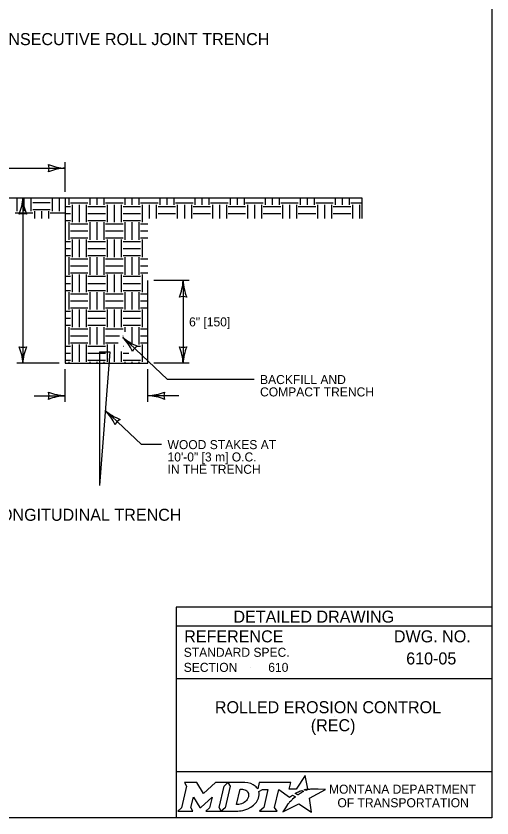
# Model space of a CAD drawing. Extents: x 49977.1 to 50021, y 49987.6 to 50011.4.
# Drawn here: x 50013.59 to 50016.75, y 49987.8 to 49993.13 of the extents above; entities that cross this region are included whole.
import ezdxf

# ---------------------------------------------------------------- set-up
doc = ezdxf.new("R2010")
doc.units = 0
for name, color, linetype in [('Default', 7, 'Continuous'), ('Level 1', 7, 'Continuous'), ('Level 2', 7, 'Continuous'), ('Level 3', 7, 'Continuous'), ('Level 5', 7, 'Continuous')]:
    doc.layers.add(name, color=color, linetype=linetype)

msp = doc.modelspace()

# ---------------------------------------------------------------- linework, layer by layer
at = {"layer": 'Default'}
for points in [[(50015.5126, 49987.9811), (50015.5023, 49987.9867), (50015.5139, 49987.9895), (50015.5255, 49987.9915), (50015.5081, 49988.0816), (50015.4486, 49987.9903), (50015.4013, 49987.9896), (50015.4116, 49988.0337), (50015.2024, 49988.0338), (50015.1923, 49987.9913), (50015.1865, 49987.9996)], [(50014.7056, 49988.0338), (50014.7197, 49988.0104), (50014.6862, 49987.8671), (50014.6605, 49987.8446), (50014.7621, 49987.8446), (50014.7486, 49987.8674), (50014.7648, 49987.9375), (50014.8085, 49987.8685), (50014.8138, 49987.8685), (50014.8889, 49987.938), (50014.8725, 49987.8669), (50014.8478, 49987.8449), (50014.9494, 49987.8449), (50014.9356, 49987.8682), (50014.9688, 49988.0106)], [(50014.9688, 49988.0106), (50014.9941, 49988.0338), (50014.9117, 49988.0338), (50014.8321, 49987.9608), (50014.7876, 49988.0335), (50014.7056, 49988.0338)], [(50015.1077, 49988.0338), (50014.9941, 49988.0338), (50015.0088, 49988.0109), (50014.9749, 49987.8671), (50014.9494, 49987.8449), (50015.06, 49987.8449)], [(50015.1317, 49987.9471), (50015.1305, 49987.939), (50015.1273, 49987.9297), (50015.1231, 49987.9215), (50015.1175, 49987.914), (50015.111, 49987.9071), (50015.1031, 49987.9008), (50015.0948, 49987.8961), (50015.0857, 49987.8922), (50015.0766, 49987.8899), (50015.0674, 49987.889), (50015.0515, 49987.889), (50015.0751, 49987.989), (50015.0911, 49987.989), (50015.0987, 49987.9884), (50015.1063, 49987.9865), (50015.1129, 49987.9835), (50015.119, 49987.9793), (50015.1238, 49987.9743), (50015.1275, 49987.9683), (50015.1302, 49987.9621), (50015.1318, 49987.9547), (50015.1318, 49987.9517), (50015.1317, 49987.9471)], [(50015.1991, 49987.9747), (50015.2237, 49987.9878), (50015.2606, 49987.9878), (50015.232, 49987.8673), (50015.2045, 49987.8446), (50015.3207, 49987.8446), (50015.3037, 49987.8675), (50015.3319, 49987.9877), (50015.4032, 49987.936), (50015.4243, 49987.9511), (50015.444, 49987.9402)], [(50015.3882, 49987.8843), (50015.3729, 49987.8599), (50015.3682, 49987.8524), (50015.3624, 49987.8438), (50015.3601, 49987.8395), (50015.4654, 49987.8926), (50015.5493, 49987.8375), (50015.5362, 49987.9302), (50015.6431, 49987.9886), (50015.5938, 49987.9894), (50015.5637, 49987.9898), (50015.5429, 49987.9901), (50015.5361, 49987.9886), (50015.5312, 49987.9874), (50015.5228, 49987.9851), (50015.5126, 49987.9811)], [(50015.4622, 49987.9535), (50015.4598, 49987.9518), (50015.4415, 49987.9614), (50015.4518, 49987.9671), (50015.4559, 49987.9693), (50015.4645, 49987.9733), (50015.4702, 49987.9759), (50015.4781, 49987.9789), (50015.4854, 49987.9816), (50015.4972, 49987.9742), (50015.4932, 49987.9721), (50015.4886, 49987.9696), (50015.4844, 49987.9674), (50015.4794, 49987.9645), (50015.4775, 49987.9634), (50015.4748, 49987.9618), (50015.4723, 49987.9604), (50015.47, 49987.9588), (50015.4674, 49987.957), (50015.4647, 49987.9552), (50015.4622, 49987.9535)], [(50015.4021, 49987.9004), (50015.4021, 49987.9004)], [(50015.1057, 49987.8522), (50015.1141, 49987.8548), (50015.1271, 49987.8602), (50015.1475, 49987.8712)]]:
    msp.add_lwpolyline(points, dxfattribs=at)
for centre, radius, start, end in [((50015.1308, 49987.9554), 0.0709, 339.5329, 15.8582), ((50015.0868, 49987.9727), 0.1183, 300.9103, 339.1383)]:
    msp.add_arc(centre, radius, start, end, dxfattribs=at)
for centre, major_axis, ratio, start_param, end_param in [((50015.1056, 49987.9864), (0.0834, -0.0037), 0.568097, 0.61298, 1.570796), ((50015.1612, 49987.9937), (0.0361, -0.0295), 0.469099, 1.225588, 1.570796), ((50015.3952, 49987.8923), (-0.00694, -0.00806), 0.008222, 0, 3.137361), ((50015.4119, 49987.9106), (-0.0098, -0.0102), 0.016458, 3.141593, 6.279097), ((50015.4329, 49987.9305), (-0.0112, -0.0097), 0.021651, 3.157348, 6.283185), ((50015.0603, 49987.9932), (0, 0.1484), 0.987302, 3.139398, 3.456847)]:
    msp.add_ellipse(centre, major_axis=major_axis, ratio=ratio, start_param=start_param, end_param=end_param, dxfattribs=at)
at = {"layer": 'Level 1'}
for p, q in [((50013.5917, 49991.9196), (50013.5917, 49991.8293)), ((50013.6383, 49991.9196), (50013.6383, 49991.8293)), ((50013.6849, 49991.9196), (50013.6849, 49991.8293)), ((50013.8247, 49991.9196), (50013.8247, 49991.8293)), ((50013.8713, 49991.9196), (50013.8713, 49991.8293)), ((50013.912, 49991.9196), (50015.8855, 49991.9196)), ((50013.9365, 49991.9196), (50013.9365, 49991.8725)), ((50014.0762, 49991.9196), (50014.0762, 49991.8725)), ((50014.1228, 49991.9196), (50014.1228, 49991.8725)), ((50014.1694, 49991.9196), (50014.1694, 49991.8725)), ((50014.3092, 49991.9196), (50014.3092, 49991.8725)), ((50014.3558, 49991.9196), (50014.3558, 49991.8725)), ((50014.4024, 49991.9196), (50014.4024, 49991.8725)), ((50014.5422, 49991.9196), (50014.5422, 49991.8725)), ((50014.5888, 49991.9196), (50014.5888, 49991.8725)), ((50014.6354, 49991.9196), (50014.6354, 49991.8725)), ((50014.7752, 49991.9196), (50014.7752, 49991.8725)), ((50014.8218, 49991.9196), (50014.8218, 49991.8725)), ((50014.8684, 49991.9196), (50014.8684, 49991.8725)), ((50015.0082, 49991.9196), (50015.0082, 49991.8725)), ((50015.0548, 49991.9196), (50015.0548, 49991.8725)), ((50015.1014, 49991.9196), (50015.1014, 49991.8725)), ((50015.2412, 49991.9196), (50015.2412, 49991.8725)), ((50015.2878, 49991.9196), (50015.2878, 49991.8725)), ((50015.3344, 49991.9196), (50015.3344, 49991.8725)), ((50015.4742, 49991.9196), (50015.4742, 49991.8725)), ((50015.5208, 49991.9196), (50015.5208, 49991.8725)), ((50015.5674, 49991.9196), (50015.5674, 49991.8725)), ((50015.7072, 49991.9196), (50015.7072, 49991.8725)), ((50015.7538, 49991.9196), (50015.7538, 49991.8725)), ((50015.8004, 49991.9196), (50015.8004, 49991.8725)), ((50015.8855, 49991.9196), (50015.8855, 49991.7821)), ((50013.6965, 49991.8876), (50013.813, 49991.8876)), ((50013.6965, 49991.841), (50013.813, 49991.841)), ((50013.912, 49991.8617), (50013.9472, 49991.8617)), ((50013.9472, 49991.885), (50014.0637, 49991.885)), ((50013.9589, 49991.8733), (50013.9589, 49991.7568)), ((50014.0055, 49991.8733), (50014.0055, 49991.7568)), ((50014.0521, 49991.8733), (50014.0521, 49991.7568)), ((50014.0637, 49991.8617), (50014.1802, 49991.8617)), ((50014.1802, 49991.885), (50014.2967, 49991.885)), ((50014.1919, 49991.8733), (50014.1919, 49991.7568)), ((50014.2385, 49991.8733), (50014.2385, 49991.7568)), ((50014.2851, 49991.8733), (50014.2851, 49991.7568)), ((50014.2967, 49991.8617), (50014.4132, 49991.8617)), ((50014.4132, 49991.885), (50014.5297, 49991.885)), ((50014.4249, 49991.8733), (50014.4249, 49991.7568)), ((50014.4715, 49991.8733), (50014.4715, 49991.7821)), ((50014.5181, 49991.8733), (50014.5181, 49991.7821)), ((50014.5297, 49991.8617), (50014.6462, 49991.8617)), ((50014.6462, 49991.885), (50014.7627, 49991.885)), ((50014.6579, 49991.8733), (50014.6579, 49991.7821)), ((50014.7045, 49991.8733), (50014.7045, 49991.7821)), ((50014.7511, 49991.8733), (50014.7511, 49991.7821)), ((50014.7627, 49991.8617), (50014.8792, 49991.8617)), ((50014.8792, 49991.885), (50014.9957, 49991.885)), ((50014.8909, 49991.8733), (50014.8909, 49991.7821)), ((50014.9375, 49991.8733), (50014.9375, 49991.7821)), ((50014.9841, 49991.8733), (50014.9841, 49991.7821)), ((50014.9957, 49991.8617), (50015.1122, 49991.8617)), ((50015.1122, 49991.885), (50015.2287, 49991.885)), ((50015.1239, 49991.8733), (50015.1239, 49991.7821)), ((50015.1705, 49991.8733), (50015.1705, 49991.7821)), ((50015.2171, 49991.8733), (50015.2171, 49991.7821)), ((50015.2287, 49991.8617), (50015.3452, 49991.8617)), ((50015.3452, 49991.885), (50015.4617, 49991.885)), ((50015.3569, 49991.8733), (50015.3569, 49991.7821)), ((50015.4035, 49991.8733), (50015.4035, 49991.7821)), ((50015.45, 49991.8733), (50015.45, 49991.7821)), ((50015.4617, 49991.8617), (50015.5782, 49991.8617)), ((50015.5782, 49991.885), (50015.6947, 49991.885)), ((50015.5898, 49991.8733), (50015.5898, 49991.7821)), ((50015.6364, 49991.8733), (50015.6364, 49991.7821)), ((50015.683, 49991.8733), (50015.683, 49991.7821)), ((50015.6947, 49991.8617), (50015.8112, 49991.8617)), ((50015.8112, 49991.885), (50015.8855, 49991.885)), ((50015.8228, 49991.8733), (50015.8228, 49991.7821)), ((50015.8694, 49991.8733), (50015.8694, 49991.7821)), ((50013.58, 49991.8185), (50013.6965, 49991.8185)), ((50013.709, 49991.8293), (50013.709, 49991.7821)), ((50013.7556, 49991.8293), (50013.7556, 49991.7821)), ((50013.8022, 49991.8293), (50013.8022, 49991.7821)), ((50013.813, 49991.8185), (50013.912, 49991.8185)), ((50013.912, 49991.8151), (50013.9472, 49991.8151)), ((50014.0637, 49991.8151), (50014.1802, 49991.8151)), ((50014.2967, 49991.8151), (50014.4132, 49991.8151)), ((50014.5297, 49991.8151), (50014.6462, 49991.8151)), ((50014.7627, 49991.8151), (50014.8792, 49991.8151)), ((50014.9957, 49991.8151), (50015.1122, 49991.8151)), ((50015.2287, 49991.8151), (50015.3452, 49991.8151)), ((50015.4617, 49991.8151), (50015.5782, 49991.8151)), ((50015.6947, 49991.8151), (50015.8112, 49991.8151)), ((50013.912, 49991.7685), (50013.9472, 49991.7685)), ((50013.9365, 49991.7568), (50013.9365, 49991.6403)), ((50013.9472, 49991.746), (50014.0637, 49991.746)), ((50014.0637, 49991.7685), (50014.1802, 49991.7685)), ((50014.0762, 49991.7568), (50014.0762, 49991.6403)), ((50014.1228, 49991.7568), (50014.1228, 49991.6403)), ((50014.1694, 49991.7568), (50014.1694, 49991.6403)), ((50014.1802, 49991.746), (50014.2967, 49991.746)), ((50014.2967, 49991.7685), (50014.4132, 49991.7685)), ((50014.3092, 49991.7568), (50014.3092, 49991.6403)), ((50014.3558, 49991.7568), (50014.3558, 49991.6403)), ((50014.4024, 49991.7568), (50014.4024, 49991.6403)), ((50014.4132, 49991.746), (50014.462, 49991.746)), ((50013.9472, 49991.6994), (50014.0637, 49991.6994)), ((50014.1802, 49991.6994), (50014.2967, 49991.6994)), ((50014.4132, 49991.6994), (50014.462, 49991.6994)), ((50013.912, 49991.6295), (50013.9472, 49991.6295)), ((50013.9472, 49991.6528), (50014.0637, 49991.6528)), ((50013.9589, 49991.6411), (50013.9589, 49991.5246)), ((50014.0055, 49991.6411), (50014.0055, 49991.5246)), ((50014.0521, 49991.6411), (50014.0521, 49991.5246)), ((50014.0637, 49991.6295), (50014.1802, 49991.6295)), ((50014.1802, 49991.6528), (50014.2967, 49991.6528)), ((50014.1919, 49991.6411), (50014.1919, 49991.5246)), ((50014.2385, 49991.6411), (50014.2385, 49991.5246)), ((50014.2851, 49991.6411), (50014.2851, 49991.5246)), ((50014.2967, 49991.6295), (50014.4132, 49991.6295)), ((50014.4132, 49991.6528), (50014.462, 49991.6528)), ((50014.4249, 49991.6411), (50014.4249, 49991.5246)), ((50013.912, 49991.5829), (50013.9472, 49991.5829)), ((50014.0637, 49991.5829), (50014.1802, 49991.5829)), ((50014.2967, 49991.5829), (50014.4132, 49991.5829)), ((50013.912, 49991.5363), (50013.9472, 49991.5363)), ((50013.9365, 49991.5246), (50013.9365, 49991.4081)), ((50014.0637, 49991.5363), (50014.1802, 49991.5363)), ((50014.0762, 49991.5246), (50014.0762, 49991.4081)), ((50014.1228, 49991.5246), (50014.1228, 49991.4081)), ((50014.1694, 49991.5246), (50014.1694, 49991.4081)), ((50014.2967, 49991.5363), (50014.4132, 49991.5363)), ((50014.3092, 49991.5246), (50014.3092, 49991.4081)), ((50014.3558, 49991.5246), (50014.3558, 49991.4081)), ((50014.4024, 49991.5246), (50014.4024, 49991.4081)), ((50013.9472, 49991.5138), (50014.0637, 49991.5138)), ((50013.9472, 49991.4672), (50014.0637, 49991.4672)), ((50014.1802, 49991.5138), (50014.2967, 49991.5138)), ((50014.1802, 49991.4672), (50014.2967, 49991.4672)), ((50014.4132, 49991.5138), (50014.462, 49991.5138)), ((50014.4132, 49991.4672), (50014.462, 49991.4672)), ((50013.9472, 49991.4206), (50014.0637, 49991.4206)), ((50014.1802, 49991.4206), (50014.2967, 49991.4206)), ((50014.4132, 49991.4206), (50014.462, 49991.4206)), ((50013.912, 49991.3973), (50013.9472, 49991.3973)), ((50013.9589, 49991.409), (50013.9589, 49991.2925)), ((50014.0055, 49991.409), (50014.0055, 49991.2925)), ((50014.0521, 49991.409), (50014.0521, 49991.2925)), ((50014.0637, 49991.3973), (50014.1802, 49991.3973)), ((50014.1919, 49991.409), (50014.1919, 49991.2925)), ((50014.2385, 49991.409), (50014.2385, 49991.2925)), ((50014.2851, 49991.409), (50014.2851, 49991.2925)), ((50014.2967, 49991.3973), (50014.4132, 49991.3973)), ((50014.4249, 49991.409), (50014.4249, 49991.2925)), ((50014.462, 49990.8196), (50014.462, 49991.3696)), ((50013.912, 49991.3507), (50013.9472, 49991.3507)), ((50014.0637, 49991.3507), (50014.1802, 49991.3507)), ((50014.2967, 49991.3507), (50014.4132, 49991.3507)), ((50013.912, 49991.3041), (50013.9472, 49991.3041)), ((50013.9365, 49991.2925), (50013.9365, 49991.176)), ((50013.9472, 49991.2816), (50014.0637, 49991.2816)), ((50014.0637, 49991.3041), (50014.1802, 49991.3041)), ((50014.0762, 49991.2925), (50014.0762, 49991.176)), ((50014.1228, 49991.2925), (50014.1228, 49991.176)), ((50014.1694, 49991.2925), (50014.1694, 49991.176)), ((50014.1802, 49991.2816), (50014.2967, 49991.2816)), ((50014.2967, 49991.3041), (50014.4132, 49991.3041)), ((50014.3092, 49991.2925), (50014.3092, 49991.176)), ((50014.3558, 49991.2925), (50014.3558, 49991.176)), ((50014.4024, 49991.2925), (50014.4024, 49991.176)), ((50014.4132, 49991.2816), (50014.462, 49991.2816)), ((50013.9472, 49991.235), (50014.0637, 49991.235)), ((50014.1802, 49991.235), (50014.2967, 49991.235)), ((50014.4132, 49991.235), (50014.462, 49991.235)), ((50013.912, 49991.1651), (50013.9472, 49991.1651)), ((50013.9472, 49991.1884), (50014.0637, 49991.1884)), ((50013.9589, 49991.1768), (50013.9589, 49991.0603)), ((50014.0055, 49991.1768), (50014.0055, 49991.0603)), ((50014.0521, 49991.1768), (50014.0521, 49991.0603)), ((50014.0637, 49991.1651), (50014.1802, 49991.1651)), ((50014.1802, 49991.1884), (50014.2967, 49991.1884)), ((50014.1919, 49991.1768), (50014.1919, 49991.0603)), ((50014.2385, 49991.1768), (50014.2385, 49991.0603)), ((50014.2851, 49991.1768), (50014.2851, 49991.0603)), ((50014.2967, 49991.1651), (50014.4132, 49991.1651)), ((50014.4132, 49991.1884), (50014.462, 49991.1884)), ((50014.4249, 49991.1768), (50014.4249, 49991.0603)), ((50013.912, 49991.1185), (50013.9472, 49991.1185)), ((50014.0637, 49991.1185), (50014.1802, 49991.1185)), ((50014.2967, 49991.1185), (50014.4132, 49991.1185)), ((50013.912, 49991.0719), (50013.9472, 49991.0719)), ((50013.9365, 49991.0603), (50013.9365, 49990.9438)), ((50013.9472, 49991.0495), (50014.0637, 49991.0495)), ((50014.0637, 49991.0719), (50014.1802, 49991.0719)), ((50014.0762, 49991.0603), (50014.0762, 49990.9438)), ((50014.1228, 49991.0603), (50014.1228, 49990.9438)), ((50014.1694, 49991.0603), (50014.1694, 49990.9438)), ((50014.1802, 49991.0495), (50014.2967, 49991.0495)), ((50014.2967, 49991.0719), (50014.4132, 49991.0719)), ((50014.3092, 49991.0603), (50014.3092, 49991.0282)), ((50014.3558, 49991.0603), (50014.3558, 49990.9438)), ((50014.4024, 49991.0603), (50014.4024, 49990.9438)), ((50014.4132, 49991.0495), (50014.462, 49991.0495)), ((50013.9472, 49991.0029), (50014.0637, 49991.0029)), ((50014.1802, 49991.0029), (50014.2738, 49991.0029)), ((50014.2966, 49991.0029), (50014.2967, 49991.0029)), ((50014.4132, 49991.0029), (50014.462, 49991.0029)), ((50013.9472, 49990.9563), (50014.0637, 49990.9563)), ((50013.9589, 49990.9446), (50013.9589, 49990.8281)), ((50014.0055, 49990.9446), (50014.0055, 49990.8281)), ((50014.0521, 49990.9446), (50014.0521, 49990.8281)), ((50014.1802, 49990.9563), (50014.265, 49990.9563)), ((50014.1919, 49990.9446), (50014.1919, 49990.8281)), ((50014.2385, 49990.9446), (50014.2385, 49990.8281)), ((50014.4132, 49990.9563), (50014.462, 49990.9563)), ((50014.4249, 49990.9446), (50014.4249, 49990.8281)), ((50013.912, 49990.933), (50013.9472, 49990.933)), ((50013.912, 49990.8864), (50013.9472, 49990.8864)), ((50014.0637, 49990.933), (50014.1802, 49990.933)), ((50014.0637, 49990.8864), (50014.1802, 49990.8864)), ((50014.2101, 49990.8949), (50014.1413, 49990.0068)), ((50014.1413, 49990.8949), (50014.1413, 49990.0068)), ((50014.1413, 49990.8949), (50014.2101, 49990.8949)), ((50014.2851, 49990.8986), (50014.2851, 49990.8281)), ((50014.2967, 49990.933), (50014.301, 49990.933)), ((50014.2967, 49990.8864), (50014.3363, 49990.8864)), ((50014.3952, 49990.933), (50014.4132, 49990.933)), ((50014.4121, 49990.8864), (50014.4132, 49990.8864)), ((50013.912, 49990.8398), (50013.9472, 49990.8398)), ((50013.9365, 49990.8281), (50013.9365, 49990.8196)), ((50014.0637, 49990.8398), (50014.1802, 49990.8398)), ((50014.0762, 49990.8281), (50014.0762, 49990.8196)), ((50014.1228, 49990.8281), (50014.1228, 49990.8196)), ((50014.1694, 49990.8281), (50014.1694, 49990.8196)), ((50014.2967, 49990.8398), (50014.4132, 49990.8398)), ((50014.3092, 49990.8281), (50014.3092, 49990.8196)), ((50014.3558, 49990.8281), (50014.3558, 49990.8196)), ((50014.4024, 49990.8281), (50014.4024, 49990.8196))]:
    msp.add_line(p, q, dxfattribs=at)
msp.add_lwpolyline([(49999.3835, 49998.9992), (50016.7501, 49998.9992), (50016.7501, 49987.7988), (49999.3835, 49987.7988)], close=True, dxfattribs=at)
msp.add_lwpolyline([(50012.812, 49991.9196), (50013.912, 49991.9196), (50013.912, 49990.8196), (50014.462, 49990.8196)], dxfattribs=at)
at = {"layer": 'Level 3'}
for p, q in [((50012.812, 49992.1159), (50013.912, 49992.1159)), ((50013.912, 49991.9596), (50013.912, 49992.1559)), ((50013.6306, 49991.9196), (50013.6306, 49990.8196)), ((50014.7361, 49991.3696), (50014.502, 49991.3696)), ((50014.6961, 49991.3696), (50014.6961, 49990.8196)), ((50014.2953, 49990.992), (50014.5931, 49990.7114)), ((50013.872, 49990.8196), (50013.5906, 49990.8196)), ((50013.912, 49990.5642), (50013.912, 49990.7796)), ((50014.462, 49990.5642), (50014.462, 49990.7796)), ((50014.7361, 49990.8196), (50014.502, 49990.8196)), ((50015.1679, 49990.7114), (50014.5931, 49990.7114)), ((50013.7055, 49990.6042), (50013.912, 49990.6042)), ((50014.6685, 49990.6042), (50014.462, 49990.6042)), ((50014.1799, 49990.5048), (50014.4193, 49990.2792)), ((50014.5527, 49990.2792), (50014.4193, 49990.2792))]:
    msp.add_line(p, q, dxfattribs=at)
for centre, radius, start, end in [((50013.9253, 49992.438), 0.3224, 247.456, 267.6395), ((50013.7261, 49992.1159), 0.0794, 342.1388, 17.8612), ((50013.9287, 49991.7784), 0.3379, 92.8273, 112.0772), ((50013.3085, 49991.9328), 0.3224, 337.456, 357.6395), ((50013.9681, 49991.9362), 0.3379, 182.8273, 202.0772), ((50013.6306, 49991.7336), 0.0794, 72.1388, 107.8612), ((50014.3739, 49991.3828), 0.3224, 337.456, 357.6395), ((50015.0336, 49991.3862), 0.3379, 182.8273, 202.0772), ((50014.6961, 49991.1836), 0.0794, 72.1388, 107.8612), ((50014.0648, 49990.7666), 0.3224, 24.16, 44.3435), ((50014.5147, 49991.249), 0.3379, 229.5313, 248.7812), ((50013.6306, 49991.0055), 0.0794, 252.1388, 287.8612), ((50013.2931, 49990.8029), 0.3379, 2.8273, 22.0772), ((50013.9528, 49990.8063), 0.3224, 157.456, 177.6395), ((50014.4307, 49990.8644), 0.0794, 118.8428, 154.5652), ((50014.6961, 49991.0055), 0.0794, 252.1388, 287.8612), ((50014.3586, 49990.8029), 0.3379, 2.8273, 22.0772), ((50015.0183, 49990.8063), 0.3224, 157.456, 177.6395), ((50013.9253, 49990.9264), 0.3224, 247.456, 267.6395), ((50013.7261, 49990.6042), 0.0794, 342.1388, 17.8612), ((50014.4453, 49990.9417), 0.3379, 272.8273, 292.0772), ((50014.648, 49990.6042), 0.0794, 162.1388, 197.8612), ((50013.9287, 49990.2667), 0.3379, 92.8273, 112.0772), ((50014.4487, 49990.2821), 0.3224, 67.456, 87.6395), ((50013.9493, 49990.2794), 0.3224, 24.16, 44.3435), ((50014.3992, 49990.7619), 0.3379, 229.5313, 248.7812), ((50014.3152, 49990.3773), 0.0794, 118.8428, 154.5652)]:
    msp.add_arc(centre, radius, start, end, dxfattribs=at)
at = {"layer": 'Level 5'}
for p, q in [((50016.7501, 49989.1988), (50014.6501, 49989.1988)), ((50014.6501, 49989.1988), (50014.6501, 49987.7988)), ((50016.7501, 49989.0738), (50014.6501, 49989.0738)), ((50016.3862, 49988.8587), (50016.3862, 49988.8587)), ((50015.1444, 49988.7993), (50015.1444, 49988.7993)), ((50016.7501, 49988.7238), (50014.6501, 49988.7238)), ((50015.7001, 49988.4747), (50015.7001, 49988.4747)), ((50016.7501, 49988.1057), (50014.6501, 49988.1057))]:
    msp.add_line(p, q, dxfattribs=at)

# ---------------------------------------------------------------- texts
at = {"layer": 'Default'}
for s, p in [('MONTANA DEPARTMENT', (50015.6663, 49987.96)), ('OF TRANSPORTATION', (50015.7225, 49987.87))]:
    msp.add_text(s, height=0.06, dxfattribs=at).set_placement(p)
at = {"layer": 'Level 2'}
for s, height, p in [('CHECK SLOT/CONSECUTIVE ROLL JOINT TRENCH', 0.08, (50012.6604, 49992.9333)), ('6" [150]', 0.06, (50014.7361, 49991.0646)), ('BACKFILL AND ', 0.06, (50015.2079, 49990.6814)), ('COMPACT TRENCH', 0.06, (50015.2079, 49990.5994)), ('WOOD STAKES AT', 0.06, (50014.5927, 49990.2492)), ('10\'-0" [3 m] O.C.', 0.06, (50014.5927, 49990.1672)), ('IN THE TRENCH', 0.06, (50014.5927, 49990.0852)), ('LONGITUDINAL TRENCH', 0.08, (50013.4192, 49989.7731)), ('610-05', 0.08, (50016.1798, 49988.8187)), ('610', 0.06, (50015.2625, 49988.7693)), ('ROLLED EROSION CONTROL ', 0.08, (50014.9075, 49988.4947)), ('(REC)', 0.08, (50015.5454, 49988.3747))]:
    msp.add_text(s, height=height, dxfattribs=at).set_placement(p)
at = {"layer": 'Level 5'}
for s, height, p in [('DETAILED DRAWING', 0.0799, (50015.0311, 49989.0963)), ('REFERENCE', 0.08, (50014.7037, 49988.9654)), ('DWG. NO.', 0.08, (50016.0979, 49988.9654)), ('STANDARD SPEC.', 0.06, (50014.7004, 49988.8694)), ('SECTION', 0.06, (50014.7004, 49988.7694))]:
    msp.add_text(s, height=height, dxfattribs=at).set_placement(p)

doc.saveas('drawing.dxf')
